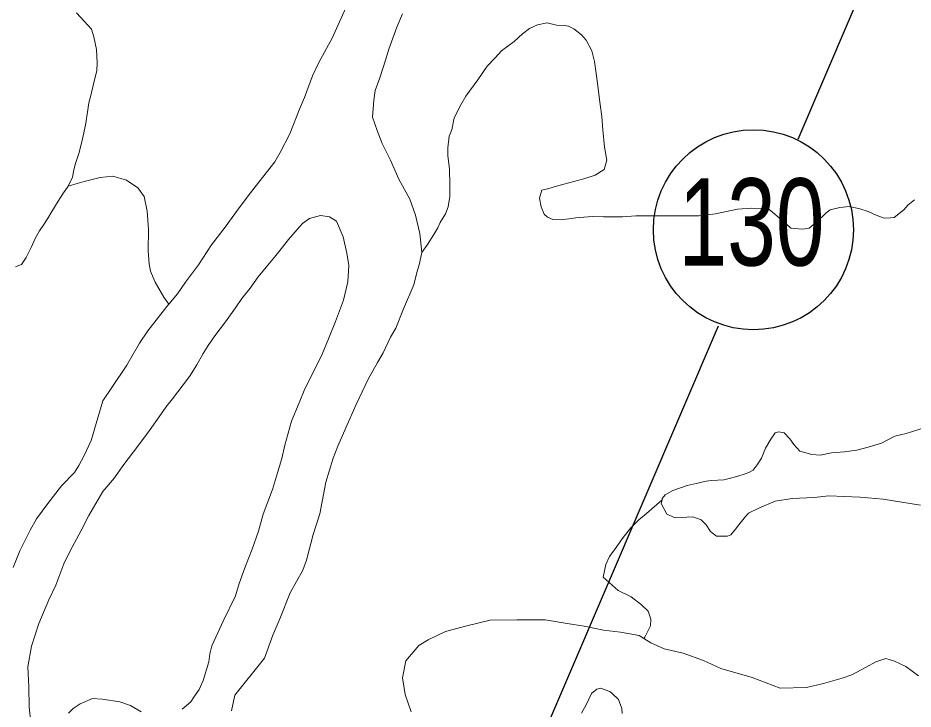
# Model space of a CAD drawing. Extents: x 553962 to 842807, y 8883888 to 9032388.
# Drawn here: x 688111 to 691702, y 8954291 to 8957065 of the extents above; entities that cross this region are included whole.
import ezdxf
from ezdxf.enums import TextEntityAlignment as Align

# ---------------------------------------------------------------- set-up
doc = ezdxf.new("R2010")
doc.units = 0
doc.header["$LTSCALE"] = 160
for name, color, linetype, lineweight in [('11', 7, 'Continuous', 25), ('15', 7, 'Continuous', 25), ('27', 7, 'Continuous', 90), ('4', 7, 'Continuous', 13)]:
    doc.layers.add(name, color=color, linetype=linetype, lineweight=lineweight)

msp = doc.modelspace()

# ---------------------------------------------------------------- linework, layer by layer
at = {"layer": '11'}
msp.add_circle((691061.1, 8956214.5), 401.3, dxfattribs=at)
at = {"layer": '15'}
for points in [[(691240.8, 8956578.2), (692809.2, 8960246.9), (693257.6, 8961326.5), (693299.9, 8961463.3), (692951.1, 8962385.1), (692776, 8962756.9), (692786.9, 8963010.2)], [(686961.1, 8947176.1), (688051.1, 8949196.4), (690022.8, 8953729), (690920.6, 8955829.2)]]:
    msp.add_lwpolyline(points, dxfattribs=at)
at = {"layer": '27'}
for points in [[(637260.6, 8972975.8), (641524.5, 8971056.2), (652526.1, 8965412.7), (653164.3, 8965062.8), (670790.5, 8953770.1), (686194, 8943929.9), (696283.3, 8937647.1)], [(694874, 8947402.7), (694491.4, 8947729), (693981.6, 8948105.1), (692654.2, 8949437.3), (691811.8, 8950292), (691552.9, 8951277.6), (691093.4, 8951755.3), (689976, 8951721.8), (689441.2, 8951996.3), (689158.9, 8952576.6), (688699.5, 8953029), (687605.5, 8953400.8), (685873.4, 8954400.8), (684752.3, 8955101.5), (681638, 8958243.7), (680641.1, 8959527.7), (679425.4, 8960995.9)]]:
    msp.add_spline(points, degree=3, dxfattribs=at)
at = {"layer": '4'}
for points in [[(689425.2, 8957102.7), (689371.6, 8956984.1), (689317.4, 8956885.8), (689292.7, 8956832.1), (689260.4, 8956745.7), (689241, 8956698.1), (689202, 8956599.3), (689162.6, 8956524.6), (689141, 8956487.3), (689091.8, 8956424.3), (689044, 8956362.6), (688998.7, 8956303.2), (688942.7, 8956225.3), (688886.9, 8956153.7), (688834.6, 8956074.3), (688782.7, 8956005.1), (688750.6, 8955958), (688716.4, 8955916.3), (688708.2, 8955906.2), (688632.5, 8955808.7), (688599, 8955759.1), (688547.7, 8955670.8), (688487.5, 8955581.6), (688451.3, 8955528.3), (688405.1, 8955368.9), (688376.4, 8955309), (688354.7, 8955269.2), (688337.2, 8955240.6), (688285.8, 8955186.6), (688231.3, 8955116.2), (688186, 8955054.3), (688160.3, 8955009.6), (688118, 8954926.1), (688091.6, 8954859.8)], [(688101.1, 8956065.9), (688125.5, 8956075.2), (688144.3, 8956103.7), (688163.4, 8956143.6), (688181.3, 8956182.3), (688197.5, 8956210.9), (688214.9, 8956235.7), (688229.6, 8956258), (688247.2, 8956287.8), (688272.7, 8956328.8), (688291.5, 8956358.6), (688312, 8956390.1), (688329.4, 8956425.8), (688335.5, 8956454.7), (688341.5, 8956481.2), (688357, 8956525), (688370.3, 8956579.1), (688382.4, 8956634.5), (688391, 8956696.3), (688395.7, 8956724.1), (688403.1, 8956753), (688416.6, 8956810.9), (688426.9, 8956852.4), (688429.3, 8956885.3), (688426.1, 8956937.4), (688415.2, 8956988.6), (688406.1, 8957019.3), (688376.8, 8957052.1), (688346.3, 8957084.9)], [(688346.3, 8957084.9), (688376.8, 8957052.1), (688406.1, 8957019.3), (688415.2, 8956988.6), (688426.1, 8956937.4), (688429.3, 8956885.3), (688426.9, 8956852.4), (688416.6, 8956810.9), (688403.1, 8956753), (688395.7, 8956724.1), (688391, 8956696.3), (688382.4, 8956634.5), (688370.3, 8956579.1), (688357, 8956525), (688341.5, 8956481.2), (688335.5, 8956454.7), (688329.4, 8956425.8), (688312, 8956390.1), (688348.8, 8956401), (688377, 8956408.9), (688441, 8956424.4), (688492, 8956430.2), (688546, 8956414.3), (688591.8, 8956383.5), (688617.2, 8956348.4), (688629.1, 8956289.6), (688634.1, 8956215.9), (688633.6, 8956129.6), (688636.8, 8956077.5), (688642.2, 8956048.1), (688660.9, 8956004.3), (688695.6, 8955944.7), (688716.4, 8955916.3), (688750.6, 8955958), (688782.7, 8956005.1), (688834.6, 8956074.3), (688886.9, 8956153.7), (688942.7, 8956225.3), (688998.7, 8956303.2), (689044, 8956362.6), (689091.8, 8956424.3), (689141, 8956487.3), (689162.6, 8956524.6), (689202, 8956599.3), (689241, 8956698.1), (689260.4, 8956745.7), (689292.7, 8956832.1), (689317.4, 8956885.8), (689371.6, 8956984.1), (689425.2, 8957102.7)], [(689375.7, 8955297.9), (689393.9, 8955346.7), (689425.6, 8955420.5), (689468.3, 8955514.1), (689516.2, 8955615.2), (689552.8, 8955682.4), (689575.8, 8955720.9), (689605.9, 8955783.3), (689627.4, 8955819.3), (689658.1, 8955896.9), (689698.3, 8955993.2), (689711.5, 8956043.5), (689720.1, 8956073.6), (689730.8, 8956124), (689723.3, 8956199.1), (689705.6, 8956273.3), (689682.5, 8956337.5), (689638.4, 8956417.7), (689605.5, 8956493.7), (689572.4, 8956560.9), (689551.3, 8956612.4), (689532.9, 8956666.3), (689537.9, 8956734.6), (689544.3, 8956773.7), (689562.6, 8956823.8), (689585.4, 8956895.3), (689598.4, 8956939.3), (689630.7, 8957028.2), (689654.1, 8957080.7)], [(689654.1, 8957080.7), (689630.7, 8957028.2), (689598.4, 8956939.3), (689585.4, 8956895.3), (689562.6, 8956823.8), (689544.3, 8956773.7), (689537.9, 8956734.6), (689532.9, 8956666.3), (689551.3, 8956612.4), (689572.4, 8956560.9), (689605.5, 8956493.7), (689638.4, 8956417.7), (689682.5, 8956337.5), (689705.6, 8956273.3), (689723.3, 8956199.1), (689730.8, 8956124), (689753.5, 8956156.2), (689779, 8956195.8), (689795.1, 8956221.9), (689804.8, 8956244.4), (689826.3, 8956279.2), (689836.2, 8956306.8), (689844, 8956348.3), (689843.1, 8956395.3), (689841.5, 8956457.5), (689835.8, 8956512.3), (689835.6, 8956544), (689841.1, 8956590.8), (689850.8, 8956615.8), (689861.4, 8956663.6), (689887.4, 8956716), (689907.6, 8956750.8), (689955.6, 8956816.3), (689993, 8956870.8), (690024.7, 8956905.2), (690051, 8956932.2), (690101.8, 8956969.8), (690134.6, 8957001.5), (690162.8, 8957022), (690195.2, 8957036.6), (690233.7, 8957044.8)], [(690460.2, 8956267), (690415.8, 8956267.3), (690380.2, 8956264.8), (690348.4, 8956262.1), (690320.3, 8956258), (690289.8, 8956255.2), (690256.8, 8956256.4), (690235.6, 8956264.8), (690222.1, 8956277.9), (690209.1, 8956306.3), (690202.8, 8956342.1), (690212.1, 8956373.6), (690240.6, 8956380.6), (690270.9, 8956389.2), (690300.8, 8956397.8), (690340.2, 8956408.5), (690381.3, 8956419), (690426.8, 8956433.3), (690462.6, 8956457), (690473.4, 8956494.4), (690463.3, 8956546.7), (690457.2, 8956616), (690453.3, 8956668.9), (690446.8, 8956717.5), (690441.4, 8956758.5), (690435.5, 8956802.6), (690430.3, 8956841.3), (690423.8, 8956890.1), (690413.6, 8956932.7), (690390.1, 8956975.7), (690371.1, 8956997.2), (690340.6, 8957020.6), (690319.7, 8957031.3), (690303.3, 8957034.9), (690271.6, 8957035.9), (690233.7, 8957044.8), (690195.2, 8957036.6), (690162.8, 8957022), (690134.6, 8957001.5), (690101.8, 8956969.8), (690051, 8956932.2), (690024.7, 8956905.2), (689993, 8956870.8), (689955.6, 8956816.3), (689907.6, 8956750.8), (689887.4, 8956716), (689861.4, 8956663.6), (689850.8, 8956615.8), (689841.1, 8956590.8), (689835.6, 8956544), (689835.8, 8956512.3), (689841.5, 8956457.5), (689843.1, 8956395.3), (689844, 8956348.3), (689836.2, 8956306.8), (689826.3, 8956279.2), (689804.8, 8956244.4), (689795.1, 8956221.9), (689779, 8956195.8), (689753.5, 8956156.2), (689730.8, 8956124), (689720.1, 8956073.6), (689711.5, 8956043.5), (689698.3, 8955993.2), (689658.1, 8955896.9), (689627.4, 8955819.3), (689605.9, 8955783.3), (689575.8, 8955720.9), (689552.8, 8955682.4), (689516.2, 8955615.2), (689468.3, 8955514.1), (689425.6, 8955420.5), (689393.9, 8955346.7), (689375.7, 8955297.9), (689345.6, 8955201.3), (689322.2, 8955075.2), (689295.1, 8954992.5), (689268.7, 8954889.4), (689253.3, 8954849.3), (689203.1, 8954757.2), (689161.4, 8954653.4), (689133.7, 8954588.4), (689100, 8954495.7), (688980.6, 8954347.7), (688967, 8954284.7)], [(690233.7, 8957044.8), (690271.6, 8957035.9), (690303.3, 8957034.9), (690319.7, 8957031.3), (690340.6, 8957020.6), (690371.1, 8956997.2), (690390.1, 8956975.7), (690413.6, 8956932.7), (690423.8, 8956890.1), (690430.3, 8956841.3), (690435.5, 8956802.6), (690441.4, 8956758.5), (690446.8, 8956717.5), (690453.3, 8956668.9), (690457.2, 8956616), (690463.3, 8956546.7), (690473.4, 8956494.4), (690462.6, 8956457), (690426.8, 8956433.3), (690381.3, 8956419), (690340.2, 8956408.5), (690300.8, 8956397.8), (690270.9, 8956389.2), (690240.6, 8956380.6), (690212.1, 8956373.6), (690202.8, 8956342.1), (690209.1, 8956306.3), (690222.1, 8956277.9), (690235.6, 8956264.8), (690256.8, 8956256.4), (690289.8, 8956255.2), (690320.3, 8956258), (690348.4, 8956262.1), (690380.2, 8956264.8), (690415.8, 8956267.3), (690460.2, 8956267), (690536.3, 8956266.9), (690589.7, 8956270.1), (690644.3, 8956270.7), (690712.8, 8956270.8), (690788.9, 8956270.7), (690842.2, 8956270.1), (690908.5, 8956279.2), (690997.9, 8956297.6), (691055.2, 8956301.9), (691112.2, 8956299.9), (691123.5, 8956297), (691180.2, 8956249.3), (691210.9, 8956221.6), (691257.7, 8956217.4), (691284.5, 8956221.5), (691317.1, 8956248.3), (691351.3, 8956281.3), (691369.5, 8956294.6), (691407.9, 8956304.7), (691446.1, 8956308.4), (691487.6, 8956298.1), (691521.5, 8956288), (691554, 8956272.9), (691585.3, 8956261.7), (691610.7, 8956262), (691626, 8956264), (691663.8, 8956294.4), (691681, 8956312.8), (691707.1, 8956334.8)], [(688091.6, 8954859.8), (688118, 8954926.1), (688160.3, 8955009.6), (688186, 8955054.3), (688231.3, 8955116.2), (688285.8, 8955186.6), (688337.2, 8955240.6), (688354.7, 8955269.2), (688376.4, 8955309), (688405.1, 8955368.9), (688451.3, 8955528.3), (688487.5, 8955581.6), (688547.7, 8955670.8), (688599, 8955759.1), (688632.5, 8955808.7), (688708.2, 8955906.2), (688716.4, 8955916.3), (688695.6, 8955944.7), (688660.9, 8956004.3), (688642.2, 8956048.1), (688636.8, 8956077.5), (688633.6, 8956129.6), (688634.1, 8956215.9), (688629.1, 8956289.6), (688617.2, 8956348.4), (688591.8, 8956383.5), (688546, 8956414.3), (688492, 8956430.2), (688441, 8956424.4), (688377, 8956408.9), (688348.8, 8956401), (688312, 8956390.1), (688291.5, 8956358.6), (688272.7, 8956328.8), (688247.2, 8956287.8), (688229.6, 8956258), (688214.9, 8956235.7), (688197.5, 8956210.9), (688181.3, 8956182.3), (688163.4, 8956143.6), (688144.3, 8956103.7), (688125.5, 8956075.2), (688101.1, 8956065.9)], [(691707.1, 8956334.8), (691681, 8956312.8), (691663.8, 8956294.4), (691626, 8956264), (691610.7, 8956262), (691585.3, 8956261.7), (691554, 8956272.9), (691521.5, 8956288), (691487.6, 8956298.1), (691446.1, 8956308.4), (691407.9, 8956304.7), (691369.5, 8956294.6), (691351.3, 8956281.3), (691317.1, 8956248.3), (691284.5, 8956221.5), (691257.7, 8956217.4), (691210.9, 8956221.6), (691180.2, 8956249.3), (691123.5, 8956297), (691112.2, 8956299.9), (691055.2, 8956301.9), (690997.9, 8956297.6), (690908.5, 8956279.2), (690842.2, 8956270.1), (690788.9, 8956270.7), (690712.8, 8956270.8), (690644.3, 8956270.7), (690589.7, 8956270.1), (690536.3, 8956266.9), (690460.2, 8956267)], [(689095, 8955073.1), (689132.7, 8955172), (689151.6, 8955239.8), (689170.1, 8955297.5), (689182.1, 8955350.4), (689208.4, 8955447.2), (689238.9, 8955520.9), (689262.4, 8955575.9), (689296.5, 8955644.5), (689330.7, 8955715.6), (689357, 8955776.8), (689384.8, 8955846.9), (689417, 8955932), (689434.8, 8956006.2), (689438.4, 8956070.8), (689430, 8956120.6), (689415.8, 8956185.8), (689388.8, 8956248.9), (689360.3, 8956266.4), (689324.9, 8956271.5), (689280.1, 8956260.3), (689252.8, 8956239.8), (689230.4, 8956216.4), (689196, 8956175.8), (689172.1, 8956144.9), (689140.2, 8956104.2), (689107.1, 8956064.7), (689074, 8956025.3), (689041.9, 8955980.8), (689008.8, 8955938.8), (688983.3, 8955901.6), (688943.3, 8955844.7), (688900.7, 8955789.1), (688874, 8955750.7), (688853.8, 8955718.4), (688828.1, 8955672.4), (688798.6, 8955626.5), (688773.3, 8955591.9), (688730.7, 8955536.3), (688704.2, 8955503), (688677.4, 8955464.6), (688641.4, 8955413.8), (688612.1, 8955373), (688574.8, 8955323.6), (688532.2, 8955268), (688497.6, 8955219.7), (688451, 8955165), (688395.8, 8955068.5), (688363.1, 8955005), (688321, 8954926.5), (688295.1, 8954874.2), (688262.9, 8954789), (688234.2, 8954730.4), (688195.3, 8954635.4), (688165.5, 8954543.8), (688151.1, 8954460.6), (688154.7, 8954380.5), (688155.6, 8954299.3), (688162.3, 8954238.2)], [(688162.3, 8954238.2), (688155.6, 8954299.3), (688154.7, 8954380.5), (688151.1, 8954460.6), (688165.5, 8954543.8), (688195.3, 8954635.4), (688234.2, 8954730.4), (688262.9, 8954789), (688295.1, 8954874.2), (688321, 8954926.5), (688363.1, 8955005), (688395.8, 8955068.5), (688451, 8955165), (688497.6, 8955219.7), (688532.2, 8955268), (688574.8, 8955323.6), (688612.1, 8955373), (688641.4, 8955413.8), (688677.4, 8955464.6), (688704.2, 8955503), (688730.7, 8955536.3), (688773.3, 8955591.9), (688798.6, 8955626.5), (688828.1, 8955672.4), (688853.8, 8955718.4), (688874, 8955750.7), (688900.7, 8955789.1), (688943.3, 8955844.7), (688983.3, 8955901.6), (689008.8, 8955938.8), (689041.9, 8955980.8), (689074, 8956025.3), (689107.1, 8956064.7), (689140.2, 8956104.2), (689172.1, 8956144.9), (689196, 8956175.8), (689230.4, 8956216.4), (689252.8, 8956239.8), (689280.1, 8956260.3), (689324.9, 8956271.5), (689360.3, 8956266.4), (689388.8, 8956248.9), (689415.8, 8956185.8), (689430, 8956120.6), (689438.4, 8956070.8), (689434.8, 8956006.2), (689417, 8955932), (689384.8, 8955846.9), (689357, 8955776.8), (689330.7, 8955715.6), (689296.5, 8955644.5), (689262.4, 8955575.9), (689238.9, 8955520.9), (689208.4, 8955447.2), (689182.1, 8955350.4), (689170.1, 8955297.5), (689151.6, 8955239.8), (689132.7, 8955172), (689095, 8955073.1), (689076.1, 8955005.2), (689050.7, 8954932.6), (689021.4, 8954857.5), (688998.9, 8954794.8), (688983.2, 8954745.9), (688934, 8954643.6), (688913.3, 8954597.4), (688888.6, 8954545), (688881.2, 8954513.5), (688876.2, 8954480.7), (688853.3, 8954406.7), (688838.1, 8954370.4), (688816.7, 8954339.5), (688804.6, 8954320.9), (688769.3, 8954290.4)], [(691749.8, 8955421.1), (691674.1, 8955397.1), (691628.1, 8955386.1), (691575.1, 8955358.8), (691520.8, 8955342.1), (691475.6, 8955330.8), (691425.9, 8955324), (691373.9, 8955319.5), (691328.7, 8955310.5), (691294.8, 8955312.7), (691247.9, 8955325.9), (691223.5, 8955353.4), (691206.5, 8955375.5), (691184.5, 8955400.4), (691163.1, 8955403.7), (691147.7, 8955400.4), (691130.3, 8955374.4), (691110, 8955338.3), (691093.4, 8955298.3), (691076, 8955271), (691060, 8955250), (691043.2, 8955240.5), (691027.7, 8955234.7), (690994.4, 8955224.4), (690963.7, 8955216.6), (690941.9, 8955211.1), (690893.6, 8955208.9), (690871.9, 8955205.9), (690831, 8955197.2), (690795.2, 8955188.3), (690737.4, 8955168.8), (690707.6, 8955150.8), (690695.7, 8955136), (690694.7, 8955131.4), (690691.2, 8955115.8), (690713.8, 8955073.2), (690747.5, 8955059.3), (690818.7, 8955063.2), (690851.2, 8955050.6), (690870.9, 8955030.9), (690888.9, 8955003.6), (690912.4, 8954985), (690956.8, 8954984.7), (690970.9, 8954990.6), (690989.5, 8955012.7), (691002.8, 8955031.3), (691029.3, 8955064.6), (691041.2, 8955076.9), (691085.1, 8955099.4), (691148.2, 8955125.1), (691217.1, 8955136.7), (691304.8, 8955139.9), (691363.4, 8955146.7), (691488.8, 8955142.3), (691581.1, 8955134), (691731.2, 8955109.7)], [(691110, 8955338.3), (691130.3, 8955374.4), (691147.7, 8955400.4), (691163.1, 8955403.7), (691184.5, 8955400.4), (691206.5, 8955375.5), (691223.5, 8955353.4), (691247.9, 8955325.9), (691294.8, 8955312.7), (691328.7, 8955310.5), (691373.9, 8955319.5), (691425.9, 8955324), (691475.6, 8955330.8), (691520.8, 8955342.1), (691575.1, 8955358.8), (691628.1, 8955386.1), (691674.1, 8955397.1), (691749.8, 8955421.1)], [(689688.7, 8954280.9), (689664.5, 8954350.2), (689652.9, 8954416.6), (689666.7, 8954484.6), (689719.6, 8954546.2), (689756, 8954569), (689825.7, 8954603.3), (689911.5, 8954625.7), (690004.8, 8954647.8), (690111.5, 8954649.1), (690225.6, 8954648.9), (690313.9, 8954634.4), (690382.1, 8954624.3), (690460.1, 8954607.7), (690528.4, 8954600.2), (690602.7, 8954586.1), (690621.4, 8954574.4), (690625.4, 8954580.3), (690648.5, 8954625.1), (690649.5, 8954651.7), (690639.2, 8954683.8), (690612.2, 8954710.1), (690570.2, 8954742.1), (690519, 8954766.7), (690458.8, 8954820.8), (690469.4, 8954871.2), (690483.2, 8954903.7), (690505.9, 8954934.6), (690538, 8954980.4), (690569.8, 8955018.6), (690601.3, 8955050.5), (690632.7, 8955076), (690694.7, 8955131.4), (690695.7, 8955136), (690707.6, 8955150.8), (690737.4, 8955168.8), (690795.2, 8955188.3), (690831, 8955197.2), (690871.9, 8955205.9), (690893.6, 8955208.9), (690941.9, 8955211.1), (690963.7, 8955216.6), (690994.4, 8955224.4), (691027.7, 8955234.7), (691043.2, 8955240.5), (691060, 8955250), (691076, 8955271), (691093.4, 8955298.3), (691110, 8955338.3)], [(688967, 8954284.7), (688980.6, 8954347.7), (689100, 8954495.7), (689133.7, 8954588.4), (689161.4, 8954653.4), (689203.1, 8954757.2), (689253.3, 8954849.3), (689268.7, 8954889.4), (689295.1, 8954992.5), (689322.2, 8955075.2), (689345.6, 8955201.3), (689375.7, 8955297.9)], [(691731.2, 8955109.7), (691581.1, 8955134), (691488.8, 8955142.3), (691363.4, 8955146.7), (691304.8, 8955139.9), (691217.1, 8955136.7), (691148.2, 8955125.1), (691085.1, 8955099.4), (691041.2, 8955076.9), (691029.3, 8955064.6), (691002.8, 8955031.3), (690989.5, 8955012.7), (690970.9, 8954990.6), (690956.8, 8954984.7), (690912.4, 8954985), (690888.9, 8955003.6), (690870.9, 8955030.9), (690851.2, 8955050.6), (690818.7, 8955063.2), (690747.5, 8955059.3), (690713.8, 8955073.2), (690691.2, 8955115.8), (690694.7, 8955131.4), (690632.7, 8955076), (690601.3, 8955050.5), (690569.8, 8955018.6), (690538, 8954980.4), (690505.9, 8954934.6), (690483.2, 8954903.7), (690469.4, 8954871.2), (690458.8, 8954820.8), (690519, 8954766.7), (690570.2, 8954742.1), (690612.2, 8954710.1), (690639.2, 8954683.8), (690649.5, 8954651.7), (690648.5, 8954625.1), (690625.4, 8954580.3), (690621.4, 8954574.4), (690649.9, 8954556.6), (690703.6, 8954533.1), (690779.1, 8954515.2), (690860.6, 8954487), (690930.5, 8954454.1), (691056.1, 8954417.9), (691168.8, 8954375.9), (691274.2, 8954378.6), (691341.9, 8954393.9), (691417.5, 8954415.4), (691456.1, 8954429.2), (691513, 8954460.2), (691551.8, 8954480.4), (691592.8, 8954494.2), (691626.7, 8954484.1), (691672.9, 8954462.2), (691723.6, 8954424.9)], [(688816.7, 8954339.5), (688838.1, 8954370.4), (688853.3, 8954406.7), (688876.2, 8954480.7), (688881.2, 8954513.5), (688888.6, 8954545), (688913.3, 8954597.4), (688934, 8954643.6), (688983.2, 8954745.9), (688998.9, 8954794.8), (689021.4, 8954857.5), (689050.7, 8954932.6), (689076.1, 8955005.2), (689095, 8955073.1)], [(691723.6, 8954424.9), (691672.9, 8954462.2), (691626.7, 8954484.1), (691592.8, 8954494.2), (691551.8, 8954480.4), (691513, 8954460.2), (691456.1, 8954429.2), (691417.5, 8954415.4), (691341.9, 8954393.9), (691274.2, 8954378.6), (691168.8, 8954375.9), (691056.1, 8954417.9), (690930.5, 8954454.1), (690860.6, 8954487), (690779.1, 8954515.2), (690703.6, 8954533.1), (690649.9, 8954556.6), (690621.4, 8954574.4), (690602.7, 8954586.1), (690528.4, 8954600.2), (690460.1, 8954607.7), (690382.1, 8954624.3), (690313.9, 8954634.4), (690225.6, 8954648.9), (690111.5, 8954649.1), (690004.8, 8954647.8), (689911.5, 8954625.7), (689825.7, 8954603.3), (689756, 8954569), (689719.6, 8954546.2), (689666.7, 8954484.6), (689652.9, 8954416.6), (689664.5, 8954350.2), (689688.7, 8954280.9)], [(690371, 8954274.6), (690390, 8954308.2), (690411.9, 8954354.3), (690432.8, 8954371.4), (690448.2, 8954375.9), (690484.5, 8954361.9), (690493.1, 8954355.3), (690520.2, 8954330.2), (690532.8, 8954294.3), (690534.7, 8954273.9)], [(690534.7, 8954273.9), (690532.8, 8954294.3), (690520.2, 8954330.2), (690493.1, 8954355.3), (690484.5, 8954361.9), (690448.2, 8954375.9), (690432.8, 8954371.4), (690411.9, 8954354.3), (690390, 8954308.2), (690371, 8954274.6)], [(688313.3, 8954274.7), (688333, 8954294.3), (688360.3, 8954312.4), (688410.5, 8954333.5), (688448.5, 8954330.9), (688519.2, 8954320.8), (688561.8, 8954305.3), (688605.3, 8954279.7)], [(688605.3, 8954279.7), (688561.8, 8954305.3), (688519.2, 8954320.8), (688448.5, 8954330.9), (688410.5, 8954333.5), (688360.3, 8954312.4), (688333, 8954294.3), (688313.3, 8954274.7)], [(688769.3, 8954290.4), (688804.6, 8954320.9), (688816.7, 8954339.5)]]:
    msp.add_lwpolyline(points, dxfattribs=at)

# ---------------------------------------------------------------- texts
at = {"layer": '11', "width": 0.75}
msp.add_text('130', height=350, dxfattribs=at).set_placement((691053.4, 8956071), align=Align.CENTER)

doc.saveas('drawing.dxf')
